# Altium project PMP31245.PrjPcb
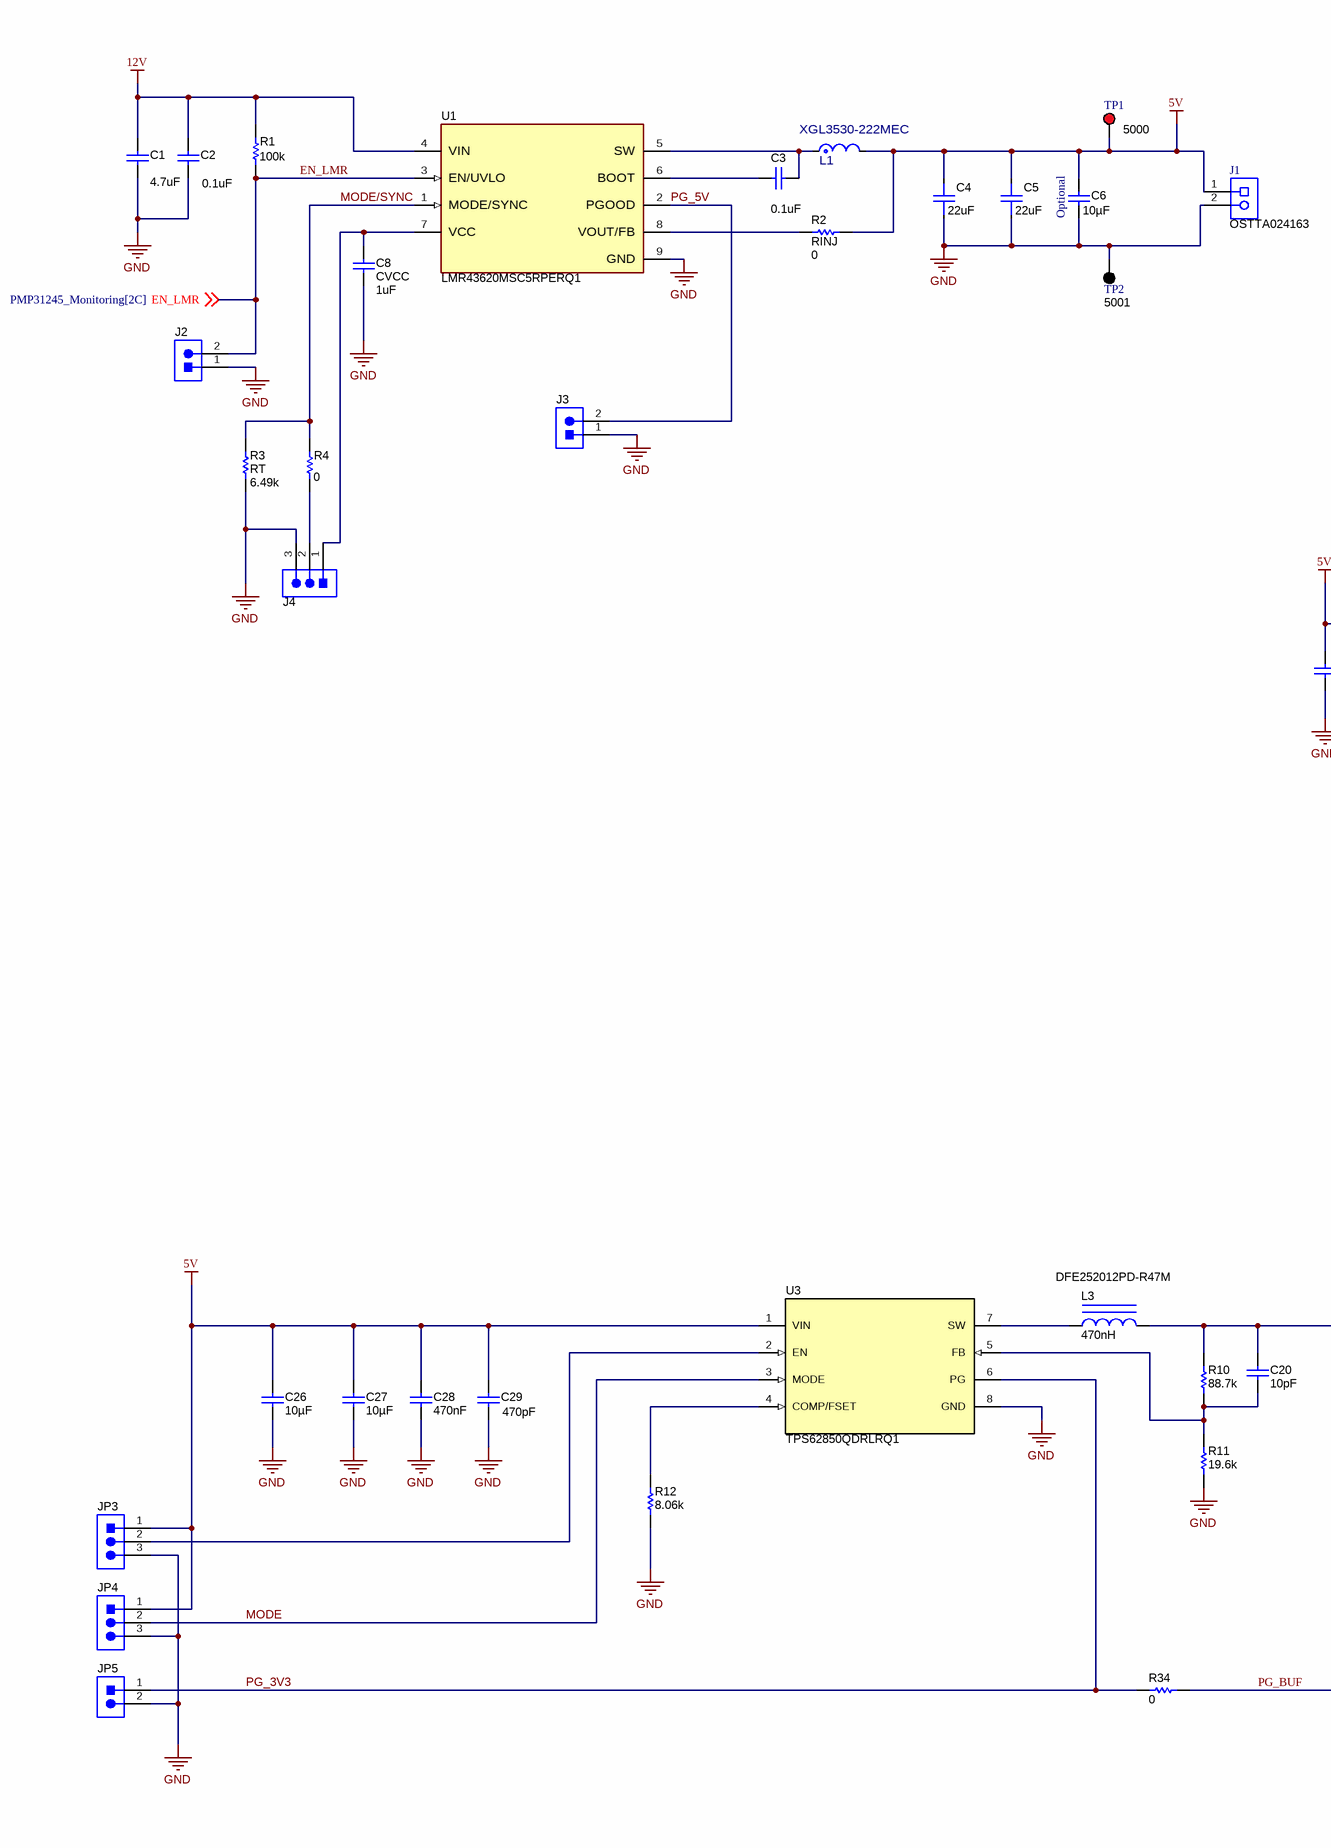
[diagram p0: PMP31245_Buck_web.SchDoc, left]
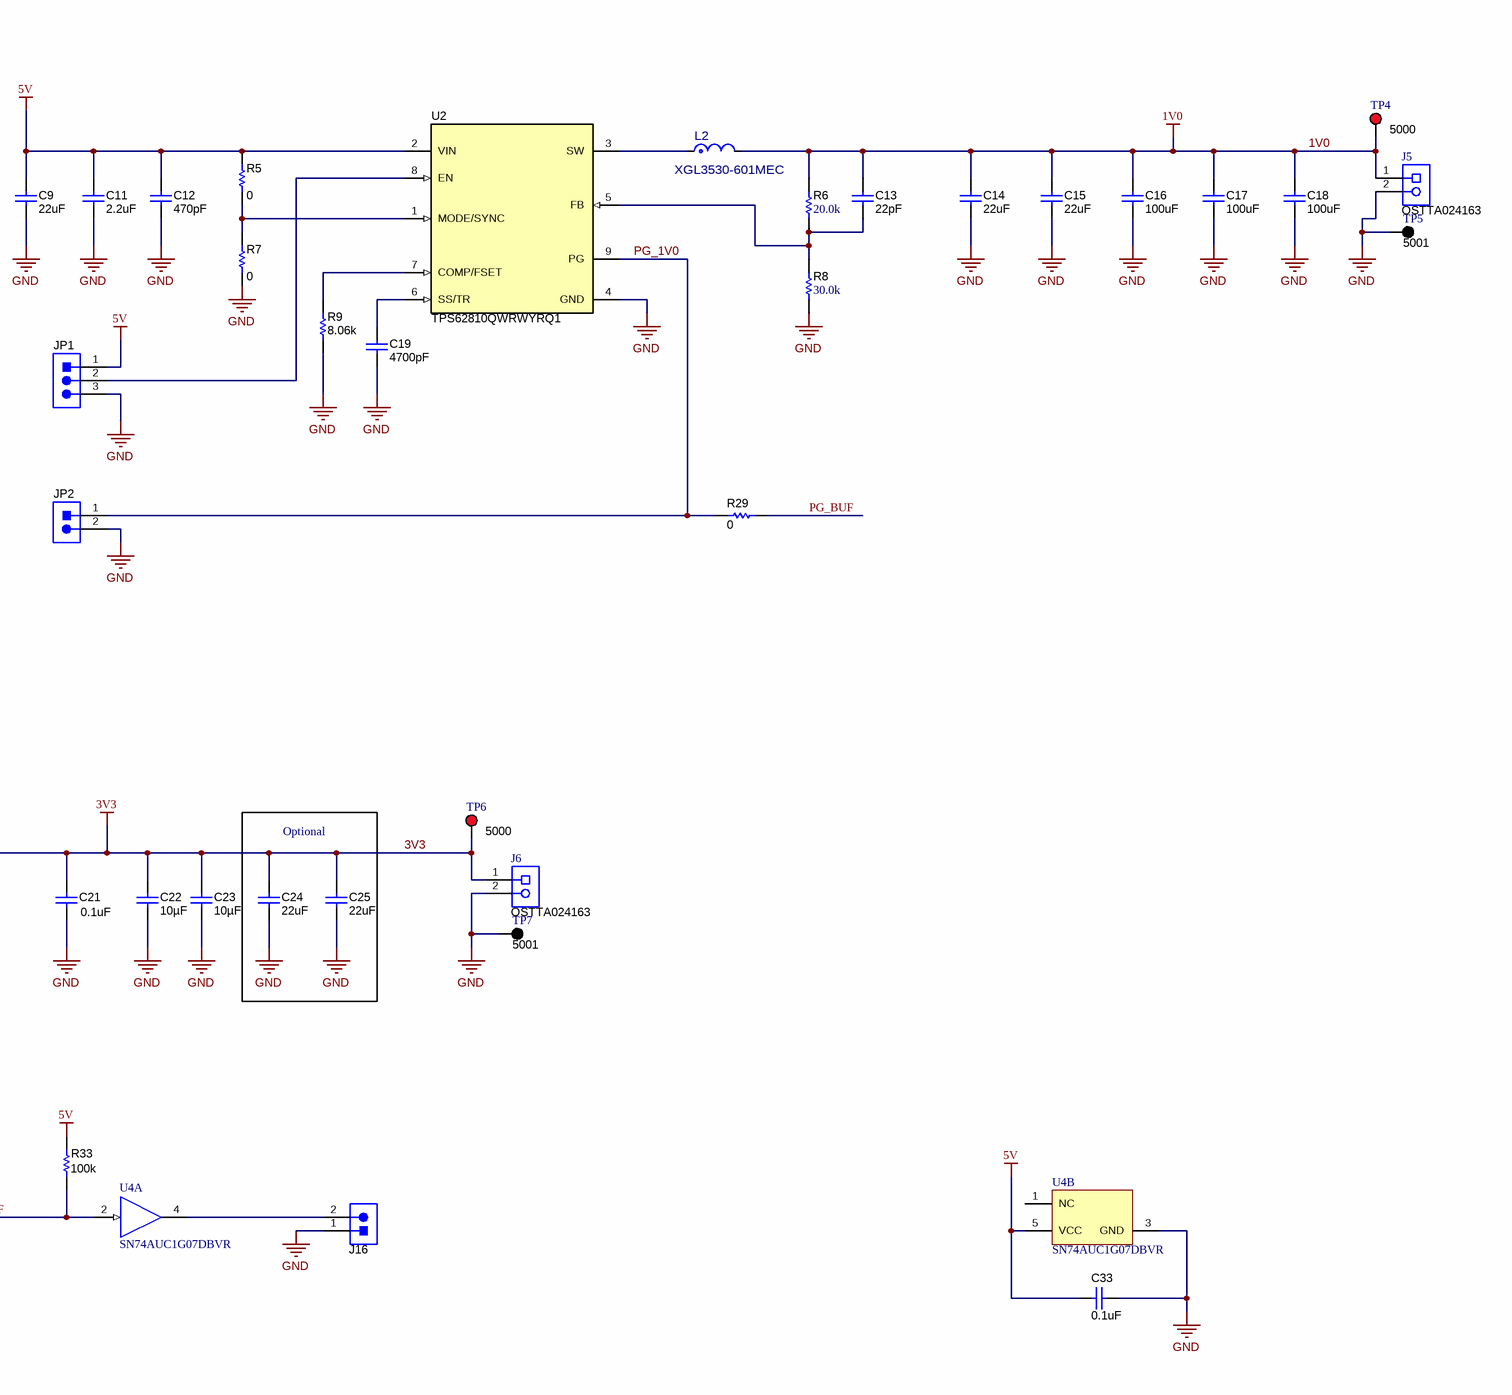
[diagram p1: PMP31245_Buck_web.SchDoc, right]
PCB_Rev: E1; SCH_Rev: E1; PRJ_Title: Automotive MCU Power Tree; PRJ_Number: PMP31245; PRJ_Engineer: Björn Görner; EVM_orderable: No; DrawnBy: Björn Görner
3 sheets, 132 parts. Net scope: global (net labels, ports and power ports of the same name join across sheets).
Board file: PMP31245.PcbDoc
Sheets:
  PMP31245_Buck_web.SchDoc
  PMP31245_Boost.SchDoc
  PMP31245_Monitoring.SchDoc

## Sheet PMP31245_Buck_web.SchDoc
size A2; Date: Not shown in title block; ApprovedBy: Not shown in title block; CheckedBy: Not shown in title block; Author: Not shown in title block; CompanyName: Not shown in title block; Engineer: Not shown in title block; Organization: Not shown in title block; Address1: Not shown in title block; Address2: Not shown in title block; Address3: Not shown in title block; Address4: Not shown in title block; DocumentNumber: 1; Revision: Use project parameter SCH_Rev; SheetNumber: 1; SheetTotal: 3; PageSetup: Record=PageOptions¦CenterHorizontal=True¦CenterVertical=True¦PrintScale=0.69¦XCorrection=1.00¦YCorrection=1.00¦PrintKind=0¦BorderSize=5000000¦LeftOffset=0¦BottomOffset=0¦Orientation=2¦PaperLength=1000¦PaperWidth=1000¦Scale=100¦PaperSource=15¦PrintQuality=600¦MediaType=1¦DitherType=10¦PaperKind=Letter¦PrintScaleMode=1

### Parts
C1  ValueDisplayed: 4.7uF  [1206_180L]  (hidden comment: CIN)
C2  ValueDisplayed: 0.1uF  [0402L]  (hidden comment: CINHF)
C3  ValueDisplayed: 0.1uF  [0402S]  (hidden comment: CB)
C4  ValueDisplayed: 22uF  [FP-GRM31CC81E226KE11L_1206-MFG]  (hidden comment: COUT1)
C5  ValueDisplayed: 22uF  [FP-GRM31CC81E226KE11L_1206-MFG]  (hidden comment: COUT2)
C6  ValueDisplayed: 10µF  [1206_190]  (hidden comment: COUT3)
C8  CVCC  ValueDisplayed: 1uF  [0603S]
C9  ValueDisplayed: 22uF  [1206_180L]  (hidden comment: GCM31CR71A226KE02)
C11  ValueDisplayed: 2.2uF  [0603L]  (hidden comment: GCM188C71A225K)
C12  ValueDisplayed: 470pF  [0402L]  (hidden comment: GCM155R71H471KA37D)
C13  ValueDisplayed: 22pF  [0402]  (hidden comment: GCM1555C1H220JA16D)
C14  ValueDisplayed: 22uF  [1206_180L]  (hidden comment: GCM31CR71A226KE02)
C15  ValueDisplayed: 22uF  [1206_180L]  (hidden comment: GCM31CR71A226KE02)
C16  ValueDisplayed: 100uF  [1210_270]  (hidden comment: GRM32ER60J107ME20L)
C17  ValueDisplayed: 100uF  [1210_270]  (hidden comment: GRM32ER60J107ME20L)
C18  ValueDisplayed: 100uF  [1210_270]  (hidden comment: GRM32ER60J107ME20L)
C19  ValueDisplayed: 4700pF  [0402]  (hidden comment: GCM155R71H472KA37D)
C20  ValueDisplayed: 10pF  [0402S]  (hidden comment: GCM1555C1H100JA16D)
C21  ValueDisplayed: 0.1uF  [0402S]  (hidden comment: C0402C104K4RACAUTO)
C22  Cap_F: 10µF  [0603]  (hidden comment: GRM188Z71A106MA73D)
C23  Cap_F: 10µF  [0603]  (hidden comment: GRM188Z71A106MA73D)
C24  ValueDisplayed: 22uF  [1206_180M]  (hidden comment: GCM31CR71A226KE02)
C25  ValueDisplayed: 22uF  [1206_180M]  (hidden comment: GCM31CR71A226KE02)
C26  Cap_F: 10µF  [0603]  (hidden comment: GRM188Z71A106MA73D)
C27  Cap_F: 10µF  [0603]  (hidden comment: GRM188Z71A106MA73D)
C28  Cap_F: 470nF  [0603S]  (hidden comment: GRM188R71C474KA88D)
C29  ValueDisplayed: 470pF  [0402S]  (hidden comment: CGA2B2X7R1H471K050BA)
C33  ValueDisplayed: 0.1uF  [0402S]  (hidden comment: C0402C104K4RACAUTO)
J1  OSTTA024163  [On-Shore_OSTTA024163]
J2  JEN  [Samtec_HTSW-102-07-G-S]  (value not drawn)
J3  JEN  [Samtec_HTSW-102-07-G-S]  (value not drawn)
J4  JMODE/SYNC  [Samtec_HTSW-103-07-G-S]  (value not drawn)
J5  OSTTA024163  [On-Shore_OSTTA024163]
J6  OSTTA024163  [On-Shore_OSTTA024163]
J16  JEN  [Samtec_HTSW-102-07-G-S]  (value not drawn)
JP1  61300311121  [WURTH_61300311121]  (value not drawn)
JP2  61300211121  [WURTH_61300211121]  (value not drawn)
JP3  61300311121  [WURTH_61300311121]  (value not drawn)
JP4  61300311121  [WURTH_61300311121]  (value not drawn)
JP5  61300211121  [WURTH_61300211121]  (value not drawn)
L1  XGL3530-222MEC  [FP-XGL3530-222MEC_SMT_IND_3MM2_3MM5-MFG]
L2  XGL3530-601MEC  [FP-XGL3530_SMT_IND_3MM2_3MM5-MFG]
L3  DFE252012PD-R47M  ValueDisplayed: 470nH  [DFE252012P]
R1  ValueDisplayed: 100k  [0402S]  (hidden comment: RENT)
R2  RINJ  ValueDisplayed: 0  [0402S]
R3  RT  ValueDisplayed: 6.49k  [0402S]
R4  ValueDisplayed: 0  [0603L]  (hidden comment: RJM)
R5  ValueDisplayed: 0  [0402S]  (hidden comment: RINJ)
R6  ValueDisplayed: 20.0k  [0402]  (hidden comment: CRCW040220K0FKED)
R7  ValueDisplayed: 0  [0402S]  (hidden comment: DNP)
R8  ValueDisplayed: 30.0k  [0402]  (hidden comment: CRCW040230K0FKED)
R9  ValueDisplayed: 8.06k  [0402]  (hidden comment: CRCW04028K06FKED)
R10  ValueDisplayed: 88.7k  [0402S]  (hidden comment: CRCW040280K6FKED)
R11  ValueDisplayed: 19.6k  [0402S]  (hidden comment: CRCW040240K2FKED)
R12  ValueDisplayed: 8.06k  [0402S]  (hidden comment: CRCW04028K06FKED)
R29  ValueDisplayed: 0  [0402S]  (hidden comment: RINJ)
R33  ValueDisplayed: 100k  [0402S]  (hidden comment: RENT)
R34  ValueDisplayed: 0  [0402S]  (hidden comment: RINJ)
TP1  5000  [Keystone5000]
TP2  5001  [Keystone5001]
TP4  5000  [Keystone5000]
TP5  5001  [Keystone5001]
TP6  5000  [Keystone5000]
TP7  5001  [Keystone5001]
U1  LMR43620MSC5RPERQ1  [RPE0009A-MFG]
U2  TPS62810QWRWYRQ1  [RWY0009A]
U3  TPS62850QDRLRQ1  [DRL0008A]
U4  SN74AUC1G07DBVR  [DBV0005A_N]  (parts A,B of 2)

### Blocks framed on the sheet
Optional: C24 C25

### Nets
1V0: C13.1 C14.1 C15.1 C16.1 C17.1 C18.1 J5.1 L2.2 R6.2 TP4.1
3V3: C20.1 C21.1 C22.1 C23.1 C24.1 C25.1 J6.1 L3.2 R10.2 TP6.1
5V: C4.2 C5.2 C6.2 C9.1 C11.1 C12.1 C26.1 C27.1 C28.1 C29.2 C33.1 J1.1 JP1.1 JP3.1 JP4.1 L1.2 R2.1 R5.1 R33.2 TP1.1 U2.2(VIN) U3.1(VIN) U4.5(VCC)
12V: C1.2 C2.1 R1.2 U1.4(VIN)
GND: C1.1 C2.2 C4.1 C5.1 C6.1 C8.2 C9.2 C11.2 C12.2 C14.2 C15.2 C16.2 C17.2 C18.2 C19.2 C21.2 C22.2 C23.2 C24.2 C25.2 C26.2 C27.2 C28.2 C29.1 C33.2 J1.2 J2.1 J3.1 J4.3 J5.2 J6.2 J16.1 JP1.3 JP2.2 JP3.3 JP4.3 JP5.2 R3.2 R7.2 R8.1 R9.1 R11.1 R12.1 TP2.1 TP5.1 TP7.1 U1.9(GND) U2.4(GND) U3.8(GND) U4.3(GND)
EN_LMR: J2.2 R1.1 U1.3(EN/UVLO) ; off-sheet EN_LMR
MODE: JP4.2 U3.3(MODE)
MODE/SYNC: R3.1 R4.2 U1.1(MODE/SYNC)
PG_1V0: JP2.1 R29.1 U2.9(PG)
PG_3V3: JP5.1 R34.1 U3.6(PG)
PG_5V: J3.2 U1.2(PGOOD)
PG_BUF: R29.2 R33.1 R34.2 U4.2(A)
NetC3_1: C3.1 U1.6(BOOT)
NetC3_2: C3.2 L1.1 U1.5(SW)
NetC8_1: C8.1 J4.1 U1.7(VCC)
NetC13_2: C13.2 R6.1 R8.2 U2.5(FB)
NetC19_1: C19.1 U2.6(SS/TR)
NetC20_2: C20.2 R10.1 R11.2 U3.5(FB)
NetJ4_2: J4.2 R4.1
NetJ16_2: J16.2 U4.4(Y)
NetJP1_2: JP1.2 U2.8(EN)
NetJP3_2: JP3.2 U3.2(EN)
NetL2_1: L2.1 U2.3(SW)
NetL3_1: L3.1 U3.7(SW)
NetR2_2: R2.2 U1.8(VOUT/FB)
NetR5_2: R5.2 R7.1 U2.1(MODE/SYNC)
NetR9_2: R9.2 U2.7(COMP/FSET)
NetR12_2: R12.2 U3.4(COMP/FSET)

Not connected (* = marked no-connect by the designer): U4 1(NC)

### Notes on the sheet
- (near C6) Optional

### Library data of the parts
C1 = CMP-0008969-2: CAP, CERM, 4.7 uF, 50 V, +/- 10%, X7R, 1206; Manufacturer: MuRata; PartNumber: GRM31CR71H475KA12L; TaMin_C: -55°C; Polarized: N; SizeAreaWB_mm2: 10.92; Value1: Unknown; U/M: EA; Value: 4.7uF; TaMax_C: 125°C; SizeZ_mm: 1.8; SizeX_mm: 3.2; SizeY_mm: 1.6; Cap_Case: 2220; Value2: 50V; SizeArea_mm2: 5.12; CompType: Capacitor; Cap_F: 4.7µF; AEC Category: Q200
C2 = CMP-0006356-2: CAP, CERM, 0.1 uF, 50 V, +/- 10%, X7R, AEC-Q200 Grade 1, 0402; Manufacturer: MuRata; PartNumber: GCM155R71H104KE02D; TaMin_C: -55°C; Polarized: N; SizeAreaWB_mm2: 3; Value1: Unknown; U/M: EA; Value: 0.1uF; TaMax_C: 125°C; SizeZ_mm: 0.6; SizeX_mm: 1; SizeY_mm: 0.5; Cap_Case: 0402; Value2: 50V; AEC Qualified: Y; Cap_F: 100nF; AEC Category: Q200
C3 = CMP-0006295-2: CAP, CERM, 0.1 uF, 25 V, +/- 20%, X7R, 0402; Manufacturer: TDK; PartNumber: C1005X7R1E104M050BB; TaMin_C: -55°C; Polarized: N; SizeAreaWB_mm2: 3; Value1: Unknown; U/M: EA; Value: 0.1uF; TaMax_C: 125°C; SizeZ_mm: 0.6; SizeX_mm: 1; SizeY_mm: 0.5; Cap_Case: 0402; Value2: 25V; CompType: Capacitor; Cap_F: 100nF; AEC Category: Q200
C4 C5 = CMP-0092611-1: Chip Multilayer Ceramic Capacitors for General Purpose, 1206, 22uF, X6S, 22%, 10%, 25V; Manufacturer: Murata; Part Number: GRM31CC81E226KE11L; Value: 22µF; AEC Qualified: No; SizeZ_mm: 1.9mm
C6 = CMP-0085950-1: CAP, CERM, 10 µF, 50 V,+/- 10%, X7R, AEC-Q200 Grade 1, 1206; Manufacturer: TDK; PartNumber: CGA5L1X7R1H106K160AC; SizeZ_mm: 1.9; Value: 10uF; Value2: 50V; Cap_Case: 1206; AEC Grade: 1; TaMin_C: -55°C; U/M: EA; CompType: Capacitor; SizeArea_mm2: 5.12; TaMax_C: 125°C; AEC Qualified: Y; AEC Category: Q200; SizeX_mm: 3.2; SizeY_mm: 1.6; Polarized: N; SizeAreaWB_mm2: 10.92
C8 = CMP-0006831-4: CAP, CERM, 1 uF, 16 V, +/- 10%, X7R, 0603; Manufacturer: Wurth Elektronik; PartNumber: 885012206052; TaMin_C: -55°C; Polarized: N; SizeAreaWB_mm2: 4.68; Value1: Unknown; U/M: EA; Value: 1uF; TaMax_C: 125°C; SizeZ_mm: 1; SizeX_mm: 1.6; SizeY_mm: 0.8; Cap_Case: 0603; Value2: 16V; SizeArea_mm2: 1.28; CompType: Capacitor; Cap_F: 1µF; AEC Category: Q200
C9 C14 C15 C24 C25 = CMP-0008811-2: CAP, CERM, 22 uF, 10 V, +/- 10%, X7R, AEC-Q200 Grade 1, 1206; Manufacturer: MuRata; Polarized: N; CompType: Capacitor; Value: 22uF; U/M: EA; Cap_F: 22µF; Value1: Unknown; VDC_V: 10V; TaMin_C: -55°C; TaMax_C: 125°C; Cap_Case: 1206; SizeArea_mm2: 5.12; SizeAreaWB_mm2: 10.92; SizeX_mm: 3.2; SizeY_mm: 1.6; SizeZ_mm: 1.8; AEC Category: Q200; AEC Qualified: Y; AEC Grade: 1
C11 = CMP-0007133-4: CAP, CERM, 2.2 uF, 10 V, +/- 10%, X7S, 0603; Manufacturer: MuRata; Alternate PartNumber: CGA3E3X7S1A225K080AB; Alternate Manufacturer: TDK; Polarized: N; CompType: Capacitor; Value: 2.2uF; U/M: EA; Cap_F: 2.2µF; Value1: Unknown; VDC_V: 10V; TaMin_C: -55°C; TaMax_C: 125°C; Cap_Case: 0603; SizeArea_mm2: 1.28; SizeAreaWB_mm2: 4.68; SizeX_mm: 1.6; SizeY_mm: 0.8; SizeZ_mm: 1; AEC Category: Q200
C12 = CMP-0006360-2: CAP, CERM, 470 pF, 50 V, +/- 10%, X7R, AEC-Q200 Grade 1, 0402; Manufacturer: MuRata; Polarized: N; CompType: Capacitor; Value: 470pF; U/M: EA; Value1: Unknown; VDC_V: 50V; TaMin_C: -55°C; TaMax_C: 125°C; Cap_Case: 0402; SizeArea_mm2: 0.5; SizeAreaWB_mm2: 3; SizeX_mm: 1; SizeZ_mm: 0.6; AEC Category: Q200; AEC Qualified: Y
C13 = CMP-0006348-2: CAP, CERM, 22 pF, 50 V, +/- 5%, C0G/NP0, AEC-Q200 Grade 1, 0402; Manufacturer: MuRata; Polarized: N; CompType: Capacitor; Value: 22pF; U/M: EA; Value1: Unknown; VDC_V: 50V; TaMin_C: -55°C; TaMax_C: 125°C; SizeArea_mm2: 0.5; SizeAreaWB_mm2: 3; SizeX_mm: 1; SizeZ_mm: 0.6; AEC Category: Q200; AEC Qualified: Y
C16-C18 = CMP-0009204-2: CAP, CERM, 100 uF, 6.3 V, +/- 20%, X5R, 1210; Manufacturer: MuRata; Polarized: N; CompType: Capacitor; Value: 100uF; U/M: EA; Cap_F: 100µF; ESR_ohm: 2m; Value1: 0.002 ohm; VDC_V: 6.3V; TaMin_C: -55°C; TaMax_C: 85°C; Cap_Case: 1210; SizeArea_mm2: 8; SizeAreaWB_mm2: 14.7; SizeX_mm: 3.2; SizeY_mm: 2.5; SizeZ_mm: 2.7; AEC Category: Q200
C19 = CMP-0006361-2: CAP, CERM, 4700 pF, 50 V, +/- 10%, X7R, AEC-Q200 Grade 1, 0402; Manufacturer: MuRata; Polarized: N; CompType: Capacitor; Value: 4700pF; U/M: EA; Cap_F: 4.7nF; Value1: Unknown; VDC_V: 50V; TaMin_C: -55°C; TaMax_C: 125°C; SizeArea_mm2: 0.5; SizeAreaWB_mm2: 3; SizeX_mm: 1; SizeZ_mm: 0.6; AEC Category: Q200; AEC Qualified: Y
C20 = CMP-0860290-1: CAP, CERM, 10 pF, 50 V,+/- 5%, C0G/NP0, AEC-Q200 Grade 1, 0402; Manufacturer: MuRata; TaMin_C: -55°C; AEC Grade: 1; AEC Qualified: Y; SizeAreaWB_mm2: 3; Cap_Case: 0402; SizeZ_mm: 0.6; Value: 10pF; TaMax_C: 125°C; Polarized: N; Value2: 50V; SizeArea_mm2: 0.5; U/M: EA; AEC Category: Q200
C21 C33 = CMP-0006237-2: CAP, CERM, 0.1 uF, 16 V, +/- 10%, X7R, AEC-Q200 Grade 1, 0402; Manufacturer: Kemet; TaMin_C: -55°C; Polarized: N; SizeAreaWB_mm2: 3; Value1: Unknown; U/M: EA; Value: 0.1uF; TaMax_C: 125°C; SizeZ_mm: 0.6; SizeX_mm: 1; SizeY_mm: 0.5; Cap_Case: 0402; Value2: 16V; AEC Qualified: Y; Cap_F: 100nF; AEC Category: Q200
C22 C23 C26 C27 = CMP-0007497-5: CAP, CERM, 10 uF, 10 V, +/- 20%, X7R, 0603; Manufacturer: MuRata; TaMin_C: -55°C; Polarized: N; SizeAreaWB_mm2: 4.68; Value1: Unknown; U/M: EA; Value: 10uF; TaMax_C: 125°C; SizeZ_mm: 1; SizeX_mm: 1.6; SizeY_mm: 0.8; Value2: 10V; SizeArea_mm2: 1.28; AEC Category: Q200
C28 = CMP-0007398-4: CAP, CERM, 0.47 uF, 16 V, +/- 10%, X7R, 0603; Manufacturer: MuRata; TaMin_C: -55°C; Polarized: N; SizeAreaWB_mm2: 4.68; Value1: Unknown; U/M: EA; Value: 0.47uF; TaMax_C: 125°C; SizeZ_mm: 1; SizeX_mm: 1.6; SizeY_mm: 0.8; Cap_Case: 0603; Value2: 16V; SizeArea_mm2: 1.28; AEC Category: Q200
C29 = CMP-0006320-2: CAP, CERM, 470 pF, 50 V, +/- 10%, X7R, AEC-Q200 Grade 1, 0402; Manufacturer: TDK; TaMin_C: -55°C; ESR_ohm: 4.96489; Polarized: N; SizeAreaWB_mm2: 3; Value1: 4.96489 ohm; U/M: EA; Value: 470pF; TaMax_C: 125°C; SizeZ_mm: 0.6; SizeX_mm: 1; SizeY_mm: 0.5; Cap_Case: 0402; Value2: 50V; AEC Qualified: Y; IRMS_A: 228.414mA; AEC Category: Q200
J1 J5 J6 = CMP-0074959-1: Terminal Block, 2x1, 5.08mm, TH; Manufacturer: On-Shore Technology; CT: True; Green_REACh: Incomplete; CNHeader: False; Green_Lifecycle: Not Set
J2 J3 J16 = CMP-0075483-1: Header, 100mil, 2x1, Gold, TH; PartNumber: HTSW-102-07-G-S; Manufacturer: Samtec; Green_REACh: Passed; CT: False; Green_Lifecycle: Active; CNHeader: True
J4 = CMP-0075484-1: Header, 100mil, 3x1, Gold, TH; PartNumber: HTSW-103-07-G-S; Manufacturer: Samtec; Green_REACh: Passed; CT: False; Green_Lifecycle: Active; CNHeader: True
JP1 JP3 JP4 = CMP-0054796-2: Header, 2.54 mm, 3x1, Gold, TH; Manufacturer: Wurth Elektronik; Pitch_mm: 2.54; Green_Lifecycle: Active; Cert_UL: Y; Shrouded: N; Green_REACh: Passed; Gender: Male; Row_Count: 1
JP2 JP5 = CMP-0054794-2: Header, 2.54 mm, 2x1, Gold, TH; Manufacturer: Wurth Elektronik; Shrouded: N; Gender: Male; Green_REACh: Passed; Pitch_mm: 2.54; Green_Lifecycle: Active; Row_Count: 1; Cert_UL: Y
L1 = CMP-0091207-1: Molded Power Inductor, Shielded, 2.2uH 20%, 7.2A, 23mOhm DCR Max, AEC-Q200, T/R; Manufacturer: Coilcraft; TaMin_C: -40°C; DCR_ohm: 23m; AEC Qualified: Yes; TaMax_C: +125°C; AEC Grade: Grade 1; Ind_H: 2.2µH; SizeZ_mm: 3mm; Shrouded: true; Isat: 1.9A; Test Frequency: 1MHz; Self Resonant Frequency: 52MHz; Material: Composite
L2 = CMP-0092762-2: Power Inductor, shielded, composite, 20% tol, SMT, RoHS, halogen-free   USD 0.580; Part Number: XGL3530-332MEC; Manufacturer: Coilcraft; Ind_H: 3.3µH; Value: 3.3uH; Self Resonant Frequency: 43MHz; TaMax_C: +125°C; TaMin_C: -40°C; AEC Qualified: Yes; Isat: 1.6A; DCR_ohm: 37.4m; SizeZ_mm: 3mm; Irms: 5.4A; Test Frequency: 1MHz; Shrouded: true; AEC Grade: Grade 1
L3 = CMP-0058944-1: Inductor, Shielded, 470 nH, 4.7 A, 0.021 ohm, SMD; Manufacturer: MuRata Toko; Isat: 6.1A @ 30% inductance drop; Irms: 4.7A @ 40C rise; SizeAreaWB_mm2: 10.5; DCR_ohm: 0.021; Value: 470nH; Imax_A: 4.7A; SizeZ_mm: 1.2; SizeX_mm: 2.5; SizeY_mm: 2; SizeArea_mm2: 5; AEC Category: Q200
R1 R33 = CMP-0025950-3: RES, 100 k, 1%, 0.063 W, AEC-Q200 Grade 0, 0402; Manufacturer: Vishay-Dale; PartNumber: CRCW0402100KFKED; Power_W: 63mW; TempCo: 100 ppm/C; Value: 100k; EIA_Code: E96; SizeX_mm: 1; SizeY_mm: 0.5; SizeZ_mm: 0.6; Value2: 0.063W; CompType: Resistor; AEC Qualified: Y; VDC_V: 50V; AEC Category: Q200; AEC Grade: 0
R2 R5 R7 R29 R34 = CMP-0026822-3: RES, 0, 5%, 0.063 W, AEC-Q200 Grade 0, 0402; Manufacturer: Vishay-Dale; PartNumber: CRCW04020000Z0ED; Power_W: 63mW; TempCo: 200 ppm/C; Value_Code: 0000; Value: 0; EIA_Code: E24; SizeX_mm: 1; SizeY_mm: 0.5; SizeZ_mm: 0.6; Value2: 0.063W; AEC Qualified: Y; VDC_V: 50V; AEC Category: Q200
R3 = CMP-0026515-2: RES, 6.49 k, 1%, 0.063 W, AEC-Q200 Grade 0, 0402; Manufacturer: Vishay-Dale; PartNumber: CRCW04026K49FKED; Power_W: 63mW; TempCo: 100 ppm/C; Value_Code: 6k49; Value: 6.49k; EIA_Code: E96; SizeX_mm: 1; SizeY_mm: 0.5; SizeZ_mm: 0.6; Value2: 0.063W; CompType: Resistor; AEC Qualified: Y; VDC_V: 50V; AEC Category: Q200; AEC Grade: 0
R4 = CMP-0025697-4: RES, 0, 5%, 0.1 W, AEC-Q200 Grade 0, 0603; Manufacturer: Vishay-Dale; PartNumber: CRCW06030000Z0EA; Power_W: 100mW; TempCo: 200 ppm/C; Value_Code: 0000; Value: 0; EIA_Code: E24; SizeX_mm: 1.6; SizeY_mm: 0.8; SizeZ_mm: 1; Value2: 0.1W; SizeArea_mm2: 1.28; AEC Qualified: Y; VDC_V: 75V; AEC Category: Q200
R6 = CMP-0026162-2: RES, 20.0 k, 1%, 0.063 W, AEC-Q200 Grade 0, 0402; Manufacturer: Vishay-Dale; Power_W: 63mW; TempCo: 100 ppm/C; Value_Code: 20k0; Value: 20.0k; EIA_Code: E96; Res_ohm: 20k; SizeX_mm: 1; SizeY_mm: 0.5; SizeZ_mm: 0.6; Value2: 0.063W; AEC Qualified: Y; VDC_V: 50V; AEC Category: Q200; AEC Grade: 0
R8 = CMP-0078244-2: RES, 30.0 k, 1%, 0.063 W, AEC-Q200 Grade 0, 0402; Manufacturer: Vishay-Dale; Power_W: 63mW; Green_Lifecycle: Active; TempCo: 100 ppm/C; Value_Code: 30k0; Green_REACh: Passed; Value: 30.0k; Res_ohm: 30k; SizeX_mm: 1; SizeY_mm: 0.5; SizeZ_mm: 0.6; Value2: 0.063W; AEC Qualified: Y; VDC_V: 50V; AEC Grade: 0; AEC Category: Q200
R9 R12 = CMP-0026588-2: RES, 8.06 k, 1%, 0.063 W, AEC-Q200 Grade 0, 0402; Manufacturer: Vishay-Dale; Value: 8.06k; Value_Code: 8k06; Power_W: 63mW; Value2: 0.063W; VDC_V: 50V; TempCo: 100 ppm/C; SizeArea_mm2: 0.5; SizeX_mm: 1; SizeZ_mm: 0.6; EIA_Code: E96; AEC Category: Q200; AEC Qualified: Y; AEC Grade: 0
R10 = CMP-0026570-2: RES, 80.6 k, 1%, 0.063 W, AEC-Q200 Grade 0, 0402; Manufacturer: Vishay-Dale; Value: 80.6k; Value_Code: 80k6; Power_W: 63mW; Value2: 0.063W; VDC_V: 50V; TempCo: 100 ppm/C; SizeArea_mm2: 0.5; SizeX_mm: 1; SizeZ_mm: 0.6; EIA_Code: E96; AEC Category: Q200; AEC Qualified: Y; AEC Grade: 0
R11 = CMP-0026367-2: RES, 40.2 k, 1%, 0.063 W, AEC-Q200 Grade 0, 0402; Manufacturer: Vishay-Dale; Value: 40.2k; Value_Code: 40k2; Power_W: 63mW; Value2: 0.063W; VDC_V: 50V; TempCo: 100 ppm/C; SizeArea_mm2: 0.5; SizeX_mm: 1; SizeZ_mm: 0.6; EIA_Code: E96; AEC Category: Q200; AEC Qualified: Y; AEC Grade: 0
TP1 TP4 TP6 = CMP-0055137-1: Test Point, Miniature, Red, TH; Manufacturer: Keystone; CNHeader: FALSE; Green_Lifecycle: Active; Green_REACh: Passed; ContactFinish: Silver; CT: TRUE
TP2 TP5 TP7 = CMP-0055138-2: Test Point, Miniature, Black, TH; Manufacturer: Keystone Electronics; ContactFinish: Silver; CNHeader: FALSE; Green_Lifecycle: Active; Green_REACh: Passed; CT: TRUE
U1 = CMP-0091397-1: 36-V, 2-A Buck Converter with 1.5 µA IQ in 2-mm x 2-mm HotRod QFN; Manufacturer: Texas Instruments; Part Number: LMR43620MSC3RPERQ1; AEC Grade: Grade 1; Max Supply Voltage: 36V; Standoff Height: 0mm; Nominal Supply Current: 0.13uA; Max Duty Cycle: 98%; Switching Frequency: 2.2MHz; Output Type: Fixed,AdjustableProgrammable; TaMin_C: -40°C; SizeZ_mm: 1mm; TaMax_C: +125°C; TJmax_C: +150°C; Number Of Outputs: 1; AEC Qualified: Yes; Output Voltage: 1-34.2V; Min Supply Voltage: 3V
U2 = CMP-0082642-1: Automotive Low Input Voltage, Adjustable-Frequency Step-down Converter, RWY0009A (VQFN-HR-9); Alternate Manufacturer: Texas Instruments; SizeAreaWB_mm2: 12; SizeZ_mm: 1; SizeX_mm: 2; SizeY_mm: 3; SizeArea_mm2: 6; CompType: IC; AEC Qualified: Y; AEC Category: Q200
U3 = CMP-0860101-1: 2.7-V to 6-V Adjustable-Frequency Step-Down Converter, DRL0008A (SOT-5X3-8); Manufacturer: Texas Instruments; AEC Category: Q200; SizeX_mm: 1.6; SizeZ_mm: 0.6; AEC Qualified: Y; SizeY_mm: 2.1; SizeArea_mm2: 3.36; CompType: IC; SizeAreaWB_mm2: 8.06
U4 = CMP-0051406-2: Single Buffer/Driver With Open-Drain Output, DBV0005A (SOT-23-5); Manufacturer: Texas Instruments; 3-State Output: No; VCC(Max)(V): 2.7; Rating: Catalog; Input Type: CMOS; Logic: True; VCC(Min)(V): 0.8; F @ Nom Voltage(Max)(Mhz): 250; tpd @ Nom Voltage(Max)(ns): 4.7,3.3,2.4,2.3,1.8; ICC @ Nom Voltage(Max)(mA): 0.01; Voltage(Nom)(V): 0.8,1.2,1.5,1.8,2.5; Output Drive (IOL/IOH)(Max)(mA): 9/-9; Bits(#): 1; AEC Category: Q200; AEC Qualified: N; CompType: IC; SizeAreaWB_mm2: 14.82; SizeArea_mm2: 8.12; SizeX_mm: 2.8; SizeY_mm: 2.9; SizeZ_mm: 1.45

## Sheet PMP31245_Boost.SchDoc
size A3; Date: Not shown in title block; ApprovedBy: Not shown in title block; CheckedBy: Not shown in title block; Author: Not shown in title block; CompanyName: Not shown in title block; Engineer: Not shown in title block; Organization: Not shown in title block; Address1: Not shown in title block; Address2: Not shown in title block; Address3: Not shown in title block; Address4: Not shown in title block; DocumentNumber: 1; Revision: Use project parameter SCH_Rev; SheetNumber: 2; SheetTotal: 2; PageSetup: Record=PageOptions¦CenterHorizontal=True¦CenterVertical=True¦PrintScale=0.69¦XCorrection=1.00¦YCorrection=1.00¦PrintKind=0¦BorderSize=5000000¦LeftOffset=0¦BottomOffset=0¦Orientation=2¦PaperLength=1000¦PaperWidth=1000¦Scale=100¦PaperSource=15¦PrintQuality=600¦MediaType=1¦DitherType=10¦PaperKind=Letter¦PrintScaleMode=1
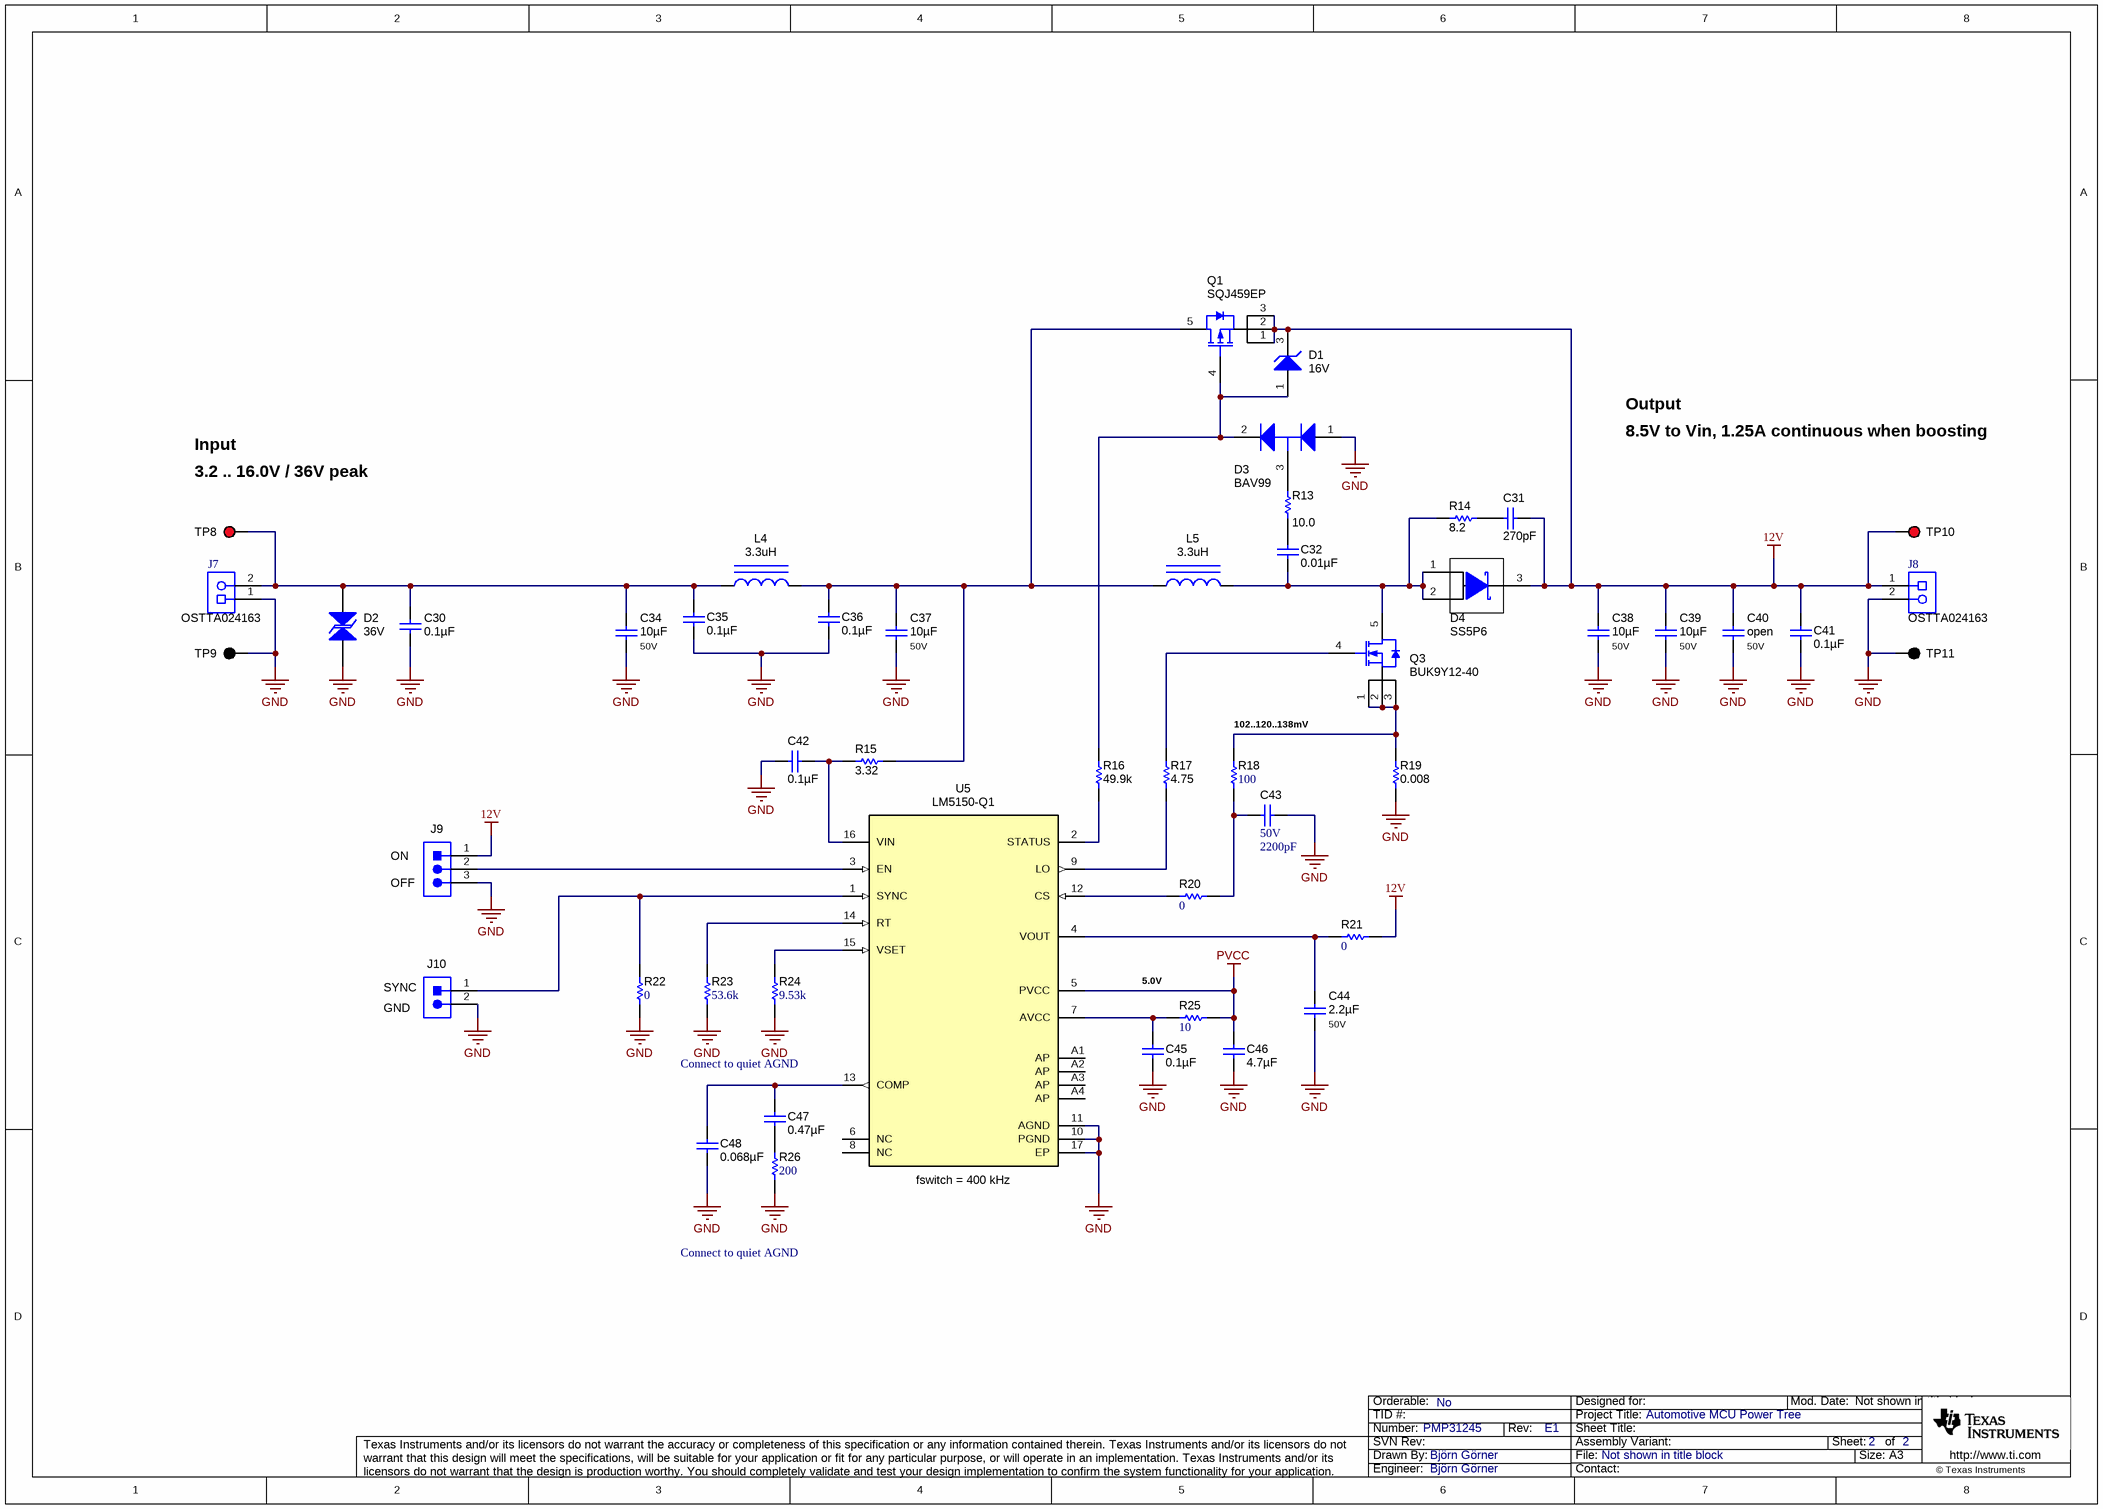
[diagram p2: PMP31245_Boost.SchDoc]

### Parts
C30  ValueDisplayed: 0.1µF  [0603]  (hidden comment: GRM188R71H104KA93D)
C31  ValueDisplayed: 270pF  [0603]  (hidden comment: GRM188R71H271KA01D)
C32  ValueDisplayed: 0.01µF  [0603]  (hidden comment: GRM188R72A103KA01D)
C34  ValueDisplayed: 10µF  Value2: 50V  [1210_270]  (hidden comment: GRM32ER71H106KA12L)
C35  ValueDisplayed: 0.1µF  [0603]  (hidden comment: GRM188R71H104KA93D)
C36  ValueDisplayed: 0.1µF  [0603]  (hidden comment: GRM188R71H104KA93D)
C37  ValueDisplayed: 10µF  Value2: 50V  [1210_270]  (hidden comment: GRM32ER71H106KA12L)
C38  ValueDisplayed: 10µF  Value2: 50V  [1210_270]  (hidden comment: GRM32ER71H106KA12L)
C39  ValueDisplayed: 10µF  Value2: 50V  [1210_270]  (hidden comment: GRM32ER71H106KA12L)
C40  ValueDisplayed: open  Value2: 50V  [1210_270]  (hidden comment: GRM32ER71H106KA12L)
C41  ValueDisplayed: 0.1µF  [0603]  (hidden comment: GRM188R71H104KA93D)
C42  ValueDisplayed: 0.1µF  [0603]  (hidden comment: GRM188R71H104KA93D)
C43  VDC_V: 50V  ValueDisplayed: 2200pF  [0402]  (hidden comment: CGA2B2X7R1H222K050BA)
C44  ValueDisplayed: 2.2µF  Value2: 50V  [1206_180]  (hidden comment: GRM31CR71H225KA88L)
C45  ValueDisplayed: 0.1µF  [0603]  (hidden comment: GRM188R71H104KA93D)
C46  ValueDisplayed: 4.7µF  [0805]  (hidden comment: GRM21BR71C475KA73L)
C47  ValueDisplayed: 0.47µF  [0603]  (hidden comment: GRM188R71E474KA12D)
C48  ValueDisplayed: 0.068µF  [0603]  (hidden comment: GRM188R71H683KA93D)
D1  value 16V  [SOT-23]  (hidden comment: BZX84C16LT1G)
D2  value 36V  [SMB]  (hidden comment: SMBJ36CA)
D3  BAV99  [SOT-23]
D4  SS5P6  [TO-277A]
J7  OSTTA024163  [On-Shore_OSTTA024163]
J8  OSTTA024163  [On-Shore_OSTTA024163]
J9  61300311121  [WURTH_61300311121]  (value not drawn)
J10  61300211121  [WURTH_61300211121]  (value not drawn)
L4  ValueDisplayed: 3.3uH  [VCHA042A]  (hidden comment: VCHA054T-3R3MS6)
L5  ValueDisplayed: 3.3uH  [VCHA042A]  (hidden comment: VCHA054T-3R3MS6)
Q1  SQJ459EP  [PowerPAK_SO-8L]
Q3  BUK9Y12-40  [PowerPAK_SO-8L]
R13  ValueDisplayed: 10.0  [0603]  (hidden comment: CRCW060310R0FKEA)
R14  ValueDisplayed: 8.2  [1206]  (hidden comment: CRCW12068R20JNEA)
R15  ValueDisplayed: 3.32  [0603]  (hidden comment: CRCW06033R32FKEA)
R16  ValueDisplayed: 49.9k  [0603]  (hidden comment: CRCW060349K9FKEA)
R17  ValueDisplayed: 4.75  [0603]  (hidden comment: CRCW06034R75FKEA)
R18  ValueDisplayed: 100  [0402]  (hidden comment: RMCF0402JT100R)
R19  ValueDisplayed: 0.008  [0612]  (hidden comment: PRL1632-R008-F-T1)
R20  ValueDisplayed: 0  [0402]  (hidden comment: ERJ-2GE0R00X)
R21  ValueDisplayed: 0  [0402]  (hidden comment: ERJ-2GE0R00X)
R22  ValueDisplayed: 0  [0402]  (hidden comment: ERJ-2GE0R00X)
R23  ValueDisplayed: 53.6k  [0402]  (hidden comment: CRCW040253K6FKED)
R24  ValueDisplayed: 9.53k  [0402]  (hidden comment: CRCW04029K53FKED)
R25  ValueDisplayed: 10  [0402]  (hidden comment: CRCW040210R0JNED)
R26  ValueDisplayed: 200  [0402]  (hidden comment: CRCW0402200RFKED)
TP8  5000  [Keystone5000]  (value not drawn)
TP9  5001  [Keystone5001]  (value not drawn)
TP10  5000  [Keystone5000]  (value not drawn)
TP11  5001  [Keystone5001]  (value not drawn)
U5  LM5150-Q1  [RUM0016C]

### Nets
12V: C31.1 C38.1 C39.1 C40.1 C41.1 D1.3(K) D4.3(K) J8.1 J9.1 Q1.1(S) Q1.2(S) Q1.3(S) R21.2 TP10.1
GND: C30.1 C34.2 C35.1 C36.1 C37.2 C38.2 C39.2 C40.2 C41.2 C42.1 C43.1 C44.2 C45.2 C46.1 C48.2 D2.1 D3.1(A) J7.1 J8.2 J9.3 J10.2 R19.1 R22.1 R23.1 R24.1 R26.1 TP9.1 TP11.1 U5.10(PGND) U5.11(AGND) U5.17(EP)
PVCC: C46.2 R25.2 U5.5(PVCC)
NetC30_2: C30.2 C34.1 C35.2 D2.2 J7.2 L4.1 TP8.1
NetC31_2: C31.2 R14.2
NetC32_1: C32.1 R13.1
NetC32_2: C32.2 D4.1(A) D4.2(A) L5.2 Q3.5(D) R14.1
NetC36_2: C36.2 C37.1 L4.2 L5.1 Q1.5(D) R15.1
NetC42_2: C42.2 R15.2 U5.16(VIN)
NetC43_2: C43.2 R18.1 R20.2
NetC44_1: C44.1 R21.1 U5.4(VOUT)
NetC45_1: C45.1 R25.1 U5.7(AVCC)
NetC47_1: C47.1 C48.1 U5.13(COMP)
NetC47_2: C47.2 R26.2
NetD1_1: D1.1(A) D3.2(K) Q1.4(G) R16.1
NetD3_3: D3.3(C) R13.2
NetJ9_2: J9.2 U5.3(EN)
NetJ10_1: J10.1 R22.2 U5.1(SYNC)
NetQ3_1: Q3.1(S) Q3.2(S) Q3.3(S) R18.2 R19.2
NetQ3_4: Q3.4(G) R17.2
NetR16_2: R16.2 U5.2(STATUS)
NetR17_1: R17.1 U5.9(LO)
NetR20_1: R20.1 U5.12(CS)
NetR23_2: R23.2 U5.14(RT)
NetR24_2: R24.2 U5.15(VSET)

Not connected (* = marked no-connect by the designer): U5 6(NC) 8(NC) A1(AP) A2(AP) A3(AP) A4(AP)

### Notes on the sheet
- Input
- Output
- 8.5V to Vin, 1.25A continuous when boosting
- (near TP8) 3.2 .. 16.0V / 36V peak
- (near R18) 102..120..138mV
- (near J9) ON
- (near J9) OFF
- (near J10) SYNC
- (near R25) 5.0V
- (near J10) GND
- Connect to quiet AGND
- (near U5) fswitch = 400 kHz

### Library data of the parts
C30 C35 C36 C41 C42 C45 = GRM188R71H104KA93D: CAP, CERM, 0.1 µF, 50 V, +/- 10%, X7R, 0603; Manufacturer: MuRata; Polarized: N; CompType: Capacitor; Value: 0.1uF; U/M: EA; Cap_F: 0.0000001; Tolerance_%: 10; Value1: Unknown; VDC_V: 50; Value2: 50V; TaMin_C: -55; TaMax_C: 125; SizeArea_mm2: 1.28; SizeAreaWB_mm2: 4.68; SizeX_mm: 1.6; SizeY_mm: 0.8; SizeZ_mm: 1; AEC Category: Q200
C31 = GRM188R71H271KA01D: CAP, CERM, 270 pF, 50 V,+/- 10%, X7R, 0603; Manufacturer: MuRata; Polarized: N; CompType: Capacitor; Value: 270pF; U/M: EA; Cap_F: 0.00000000027; Tolerance_%: 10; VDC_V: 50; Value2: 50V; TaMin_C: -55; TaMax_C: 125; SizeArea_mm2: 1.28; SizeAreaWB_mm2: 4.68; SizeX_mm: 1.6; SizeY_mm: 0.8; SizeZ_mm: 1; AEC Category: Q200
C32 = GRM188R72A103KA01D: CAP, CERM, 0.01 µF, 100 V, +/- 10%, X7R, 0603; Manufacturer: MuRata; Polarized: N; CompType: Capacitor; Value: 0.01uF; U/M: EA; Cap_F: 0.00000001; Tolerance_%: 10; Value1: Unknown; VDC_V: 100; Value2: 100V; TaMin_C: -55; TaMax_C: 125; SizeArea_mm2: 1.28; SizeAreaWB_mm2: 4.68; SizeX_mm: 1.6; SizeY_mm: 0.8; SizeZ_mm: 1; AEC Category: Q200
C34 C37-C40 = GRM32ER71H106KA12L: CAP, CERM, 10 µF, 50 V, +/- 10%, X7R, 1210; Manufacturer: MuRata; Polarized: N; CompType: Capacitor; Value: 10uF; U/M: EA; Cap_F: 0.00001; Tolerance_%: 10; Value1: Unknown; VDC_V: 50; TaMin_C: -55; TaMax_C: 125; Cap_Case: 1210; SizeArea_mm2: 8; SizeAreaWB_mm2: 14.7; SizeX_mm: 3.2; SizeY_mm: 2.5; SizeZ_mm: 2.7; AEC Category: Q200
C43 = CMP-0006317-2: CAP, CERM, 2200 pF, 50 V, +/- 10%, X7R, AEC-Q200 Grade 1, 0402; Manufacturer: TDK; TaMin_C: -55°C; ESR_ohm: 1.0779; Polarized: N; SizeAreaWB_mm2: 3; Value1: 1.07794 ohm; U/M: EA; Value: 2200pF; TaMax_C: 125°C; SizeZ_mm: 0.6; SizeX_mm: 1; SizeY_mm: 0.5; AEC Qualified: Y; Cap_F: 2.2nF; IRMS_A: 264.071mA; AEC Category: Q200
C44 = GRM31CR71H225KA88L: CAP, CERM, 2.2 µF, 50 V, +/- 10%, X7R, 1206; Manufacturer: MuRata; Polarized: N; CompType: Capacitor; Value: 2.2uF; U/M: EA; Cap_F: 0.0000022; Tolerance_%: 10; Value1: Unknown; VDC_V: 50; TaMin_C: -55; TaMax_C: 125; Cap_Case: 1206; SizeArea_mm2: 5.12; SizeAreaWB_mm2: 10.92; SizeX_mm: 3.2; SizeY_mm: 1.6; SizeZ_mm: 1.8; AEC Category: Q200
C46 = GRM21BR71C475KA73L: CAP, CERM, 4.7 µF, 16 V, +/- 10%, X7R, 0805; Manufacturer: MuRata; Polarized: N; CompType: Capacitor; Value: 4.7uF; U/M: EA; Cap_F: 0.0000047; Tolerance_%: 10; ESR_ohm: 0.006; Value1: 0.006 ohm; VDC_V: 16; Value2: 16V; TaMin_C: -55; TaMax_C: 125; SizeArea_mm2: 2.5; SizeAreaWB_mm2: 6.75; SizeX_mm: 2; SizeY_mm: 1.25; SizeZ_mm: 1.45; AEC Category: Q200
C47 = GRM188R71E474KA12D: CAP, CERM, 0.47 µF, 25 V,+/- 10%, X7R, 0603; Manufacturer: MuRata; Polarized: N; CompType: Capacitor; Value: 0.47uF; U/M: EA; Cap_F: 0.00000047; Tolerance_%: 10; VDC_V: 25; Value2: 25V; TaMin_C: -55; TaMax_C: 125; SizeArea_mm2: 1.28; SizeAreaWB_mm2: 4.68; SizeX_mm: 1.6; SizeY_mm: 0.8; SizeZ_mm: 1; AEC Category: Q200; Green_Lifecycle: Active; Green_REACh: Passed
C48 = GRM188R71H683KA93D: CAP, CERM, 0.068 µF, 50 V,+/- 10%, X7R, 0603; Manufacturer: MuRata; Polarized: N; CompType: Capacitor; Value: 0.068uF; U/M: EA; Cap_F: 0.000000068; Tolerance_%: 10; VDC_V: 50; Value2: 50V; TaMin_C: -55; TaMax_C: 125; SizeArea_mm2: 1.28; SizeAreaWB_mm2: 4.68; SizeX_mm: 1.6; SizeY_mm: 0.8; SizeZ_mm: 1; AEC Category: Q200; Green_Lifecycle: Active; Green_REACh: Passed
D1 = BZX84C16LT1G: Diode, Zener, 16 V, 225 mW, SOT-23; Manufacturer: ON Semiconductor; U/M: EA; Power_W: 0.225; Vz_V: 16; Value1: 0.225W; RJA_CperW: 556; SizeAreaWB_mm2: 14; SizeArea_mm2: 7.5; SizeX_mm: 2.5; SizeY_mm: 3; SizeZ_mm: 1.1; AEC Category: Q101
D2 = SMBJ33CA-13-F: Diode, TVS, Bi, 36 V, SMB; Manufacturer: Vishay-Semiconductor; U/M: EA; Power_W: 5; Vr_V: 36; Value1: 5W; SizeAreaWB_mm2: 44.156; SizeArea_mm2: 21.336; SizeX_mm: 5.6; SizeY_mm: 3.81; SizeZ_mm: 2.6; AEC Category: Q101
D3 = BAV99-7-F: Diode, Switching, 75 V, 0.3 A, SOT-23; Manufacturer: Diodes Inc.; SymbolCreator: a0412235; U/M: EA; Vf_V: 1.25; Value: 75V; Value1: 0.3A; Value2: 1.25V; Io_A: 0.3; Vr_V: 75; TJmax_C: 150; SizeAreaWB_mm2: 14; SizeArea_mm2: 7.5; SizeX_mm: 2.5; SizeY_mm: 3; SizeZ_mm: 1.1; AEC Category: Q101
D4 = SS5P6-M3/86A: Diode, Schottky, 60 V, 5 A, TO-277A; Manufacturer: Vishay-Semiconductor; U/M: EA; Vf_V: 0.69; Value: 60V; Value1: 5A; Value2: 0.69V; Io_A: 5; Vr_V: 60; TJmax_C: 150; SizeAreaWB_mm2: 57.375; SizeArea_mm2: 30.875; SizeX_mm: 6.5; SizeY_mm: 4.75; SizeZ_mm: 1.2; AEC Category: Q101; Green_Lifecycle: Not Set; Green_REACh: Incomplete
J7 J8 = CMP-0074959-1: as J1 on sheet PMP31245_Buck_web
J9 = 61300311121: Header, 2.54 mm, 3x1, Gold, TH; Manufacturer: Wurth Elektronik; SymbolCreator: a0799628; Green_Lifecycle: Active; Green_REACh: Passed
J10 = 61300211121: Header, 2.54 mm, 2x1, Gold, TH; Manufacturer: Wurth Elektronik; SymbolCreator: a0412235; Green_Lifecycle: Active; Green_REACh: Passed
L4 L5 = VCHA042A-1R0MS6: Inductor, 3.3 µH, 8.8 A, 0.028 ohm, AEC-Q200 Grade 0, SMD; Manufacturer: Cyntec; Value: 3.3uH; Imax_A: 8.8; DCR_ohm: 0.028; AEC Category: Q200; AEC Qualified: Y; AEC Grade: 0
Q1 = SQJ469EP-T1-GE3: MOSFET, P-CH, -60 V, -52 A, AEC-Q101, PowerPAK_SO-8L; PartNumber: SQJ459EP-T1_GE3; Manufacturer: Vishay-Siliconix; Alternate Manufacturer: None; SymbolCreator: a0411947; U/M: EA; ChType: P; Value: -60V; Value1: ? ohm; Value2: 73 nC; QgTyp_nC: 73; Vgs_V: -20; SizeAreaWB_mm2: 58.1095; SizeArea_mm2: 31.5495; SizeX_mm: 6.15; SizeY_mm: 5.13; SizeZ_mm: 1.14; AEC Category: Q101; AEC Qualified: Y
Q3 = SQJA60EP: MOSFET, N-CH, 60 V, 23 A, AEC-Q101, PowerPAK_SO-8L; PartNumber: SQJ158EP; Manufacturer: Vishay-Siliconix; Alternate Manufacturer: None; SymbolCreator: a0412235; U/M: EA; ChType: N; Value: 60V; VdsMax_V: 60; Value1: 0.03 ohm; Rdson45_ohm: 0.03; Value2: 17 nC; QgTyp_nC: 17; Vgs_V: 20; IdsMax_A: 23; SizeAreaWB_mm2: 58.1095; SizeArea_mm2: 31.5495; SizeX_mm: 6.15; SizeY_mm: 5.13; SizeZ_mm: 1.14; AEC Category: Q101; AEC Qualified: Y
R13 = CRCW060310R0FKEA: RES, 10.0, 1%, 0.1 W, 0603; Manufacturer: Vishay-Dale; CompType: Resistor; Value: 10.0; Res_ohm: 10; Value_Code: 10R0; Tolerance_%: 1; Power_W: 0.1; Value2: 0.1W; VDC_V: 75; TempCo: 100 ppm/C; SizeArea_mm2: 1.28; SizeX_mm: 1.6; SizeY_mm: 0.8; EIA_Code: E96; U/M: EA; AEC Category: Q200
R14 = CRCW12068R20JNEA: RES, 8.2, 5%, 0.25 W, 1206; Manufacturer: Vishay-Dale; CompType: Resistor; Value: 8.2; Value_Code: 8R20; Tolerance_%: 5; Power_W: 0.25; Value2: 0.25W; VDC_V: 200; TempCo: 200 ppm/C; SizeArea_mm2: 5.12; SizeX_mm: 3.2; SizeY_mm: 1.6; SizeZ_mm: 1.35; EIA_Code: E24; U/M: EA; AEC Category: Q200
R15 = CRCW06033R32FKEA: RES, 3.32, 1%, 0.1 W, 0603; Manufacturer: Vishay-Dale; CompType: Resistor; Value: 3.32; Value_Code: 3R32; Tolerance_%: 1; Power_W: 0.1; Value2: 0.1W; VDC_V: 75; TempCo: 100 ppm/C; SizeArea_mm2: 1.28; SizeX_mm: 1.6; SizeY_mm: 0.8; EIA_Code: E96; U/M: EA; AEC Category: Q200
R16 = CRCW060349K9FKEA: RES, 49.9 k, 1%, 0.1 W, 0603; Manufacturer: Vishay-Dale; CompType: Resistor; Value: 49.9k; Res_ohm: 49900; Value_Code: 49k9; Tolerance_%: 1; Power_W: 0.1; Value2: 0.1W; VDC_V: 75; TempCo: 100 ppm/C; EIA_Code: E96; U/M: EA; AEC Category: Q200; SizeArea_mm2: 1.28; SizeX_mm: 1.6; SizeY_mm: 0.8
R17 = CRCW06034R75FKEA: RES, 4.75, 1%, 0.1 W, 0603; Manufacturer: Vishay-Dale; CompType: Resistor; Value: 4.75; Value_Code: 4R75; Tolerance_%: 1; Power_W: 0.1; Value2: 0.1W; VDC_V: 75; TempCo: 100 ppm/C; SizeArea_mm2: 1.28; SizeX_mm: 1.6; SizeY_mm: 0.8; EIA_Code: E96; U/M: EA; AEC Category: Q200; Green_Lifecycle: Active; Green_REACh: Passed
R18 = CMP-0026763-1: RES, 100, 1%, 0.063 W, AEC-Q200 Grade 0, 0402; Manufacturer: Stackpole Electronics Inc; Power_W: 63mW; TempCo: 100 ppm/C; Value_Code: 100R; U/M: EA; Value: 100; EIA_Code: E96; SizeX_mm: 1; SizeY_mm: 0.5; SizeZ_mm: 0.6; Value2: 0.063W; AEC Qualified: Y; AEC Grade: 0; AEC Category: Q200
R19 = PRL1632-R008-F-T1: RES, 0.008, 1%, 1 W, 0612; Manufacturer: Susumu Co Ltd; CompType: Resistor; Value: 0.008; Value_Code: 8L000; Tolerance_%: 1; Value2: 1W; TempCo: 350 ppm/C; SizeArea_mm2: 5.12; SizeAreaWB_mm2: 10.92; SizeX_mm: 1.6; SizeY_mm: 3.2; SizeZ_mm: 0.85; EIA_Code: E96; U/M: EA; AEC Category: Q200
R20-R22 = CMP-0026992-3: RES, 0, 5%, 0.1 W, AEC-Q200 Grade 0, 0402; Manufacturer: Panasonic; Power_W: 100mW; TempCo: 600 ppm/C; Value_Code: 0000; Value: 0; EIA_Code: E24; SizeX_mm: 1; SizeY_mm: 0.5; SizeZ_mm: 0.6; Value2: 0.1W; AEC Qualified: Y; VDC_V: 50V; AEC Category: Q200; SizeAreaWB_mm2: 3
R23 = CMP-0026445-2: RES, 53.6 k, 1%, 0.063 W, AEC-Q200 Grade 0, 0402; Manufacturer: Vishay-Dale; Power_W: 63mW; TempCo: 100 ppm/C; Value_Code: 53k6; Value: 53.6k; EIA_Code: E96; SizeX_mm: 1; SizeY_mm: 0.5; SizeZ_mm: 0.6; Value2: 0.063W; AEC Qualified: Y; VDC_V: 50V; AEC Category: Q200; AEC Grade: 0
R24 = CMP-0026621-3: RES, 9.53 k, 1%, 0.063 W, AEC-Q200 Grade 0, 0402; Manufacturer: Vishay-Dale; Value_Code: 9k53; SizeX_mm: 1; Value: 9.53k; SizeY_mm: 0.5; AEC Category: Q200; AEC Qualified: Y; TempCo: 100 ppm/C; Power_W: 63mW; AEC Grade: 0; Value2: 0.063W; EIA_Code: E96; SizeZ_mm: 0.6; VDC_V: 50V
R25 = CMP-0026827-3: RES, 10, 5%, 0.063 W, AEC-Q200 Grade 0, 0402; Manufacturer: Vishay-Dale; Power_W: 63mW; TempCo: 200 ppm/C; Value_Code: 10R0; Value: 10; EIA_Code: E24; SizeX_mm: 1; SizeY_mm: 0.5; SizeZ_mm: 0.6; Value2: 0.063W; AEC Qualified: Y; VDC_V: 50V; AEC Category: Q200; AEC Grade: 0
R26 = CMP-0026159-2: RES, 200, 1%, 0.063 W, AEC-Q200 Grade 0, 0402; Manufacturer: Vishay-Dale; Power_W: 63mW; TempCo: 100 ppm/C; Value_Code: 200R; Value: 200; EIA_Code: E96; SizeX_mm: 1; SizeY_mm: 0.5; SizeZ_mm: 0.6; Value2: 0.063W; AEC Qualified: Y; VDC_V: 50V; AEC Category: Q200; AEC Grade: 0
TP8 TP10 = 5000: Test Point, Miniature, Red, TH; Manufacturer: Keystone; CompType: Test Point Loop; ContactFinish: Silver
TP9 TP11 = 5001: Test Point, Miniature, Black, TH; Manufacturer: Keystone; CompType: Test Point Loop; ContactFinish: Silver
U5 = LM5150RUMQ1: Wide VIN Automotive Low IQ Boost Controller, RUM0016C (WQFN-16); Manufacturer: Texas Instruments; SymbolCreator: a0411947; SizeArea_mm2: 16; SizeAreaWB_mm2: 25; SizeX_mm: 4; SizeZ_mm: 0.8; CompType: IC; U/M: EA

## Sheet PMP31245_Monitoring.SchDoc
size A4; Date: Not shown in title block; ApprovedBy: Not shown in title block; CheckedBy: Not shown in title block; Author: Not shown in title block; CompanyName: Not shown in title block; Engineer: Not shown in title block; Organization: Not shown in title block; Address1: Not shown in title block; Address2: Not shown in title block; Address3: Not shown in title block; Address4: Not shown in title block; DocumentNumber: 1; Revision: Use project parameter SCH_Rev; SheetNumber: 1; SheetTotal: 1; PageSetup: Record=PageOptions¦CenterHorizontal=True¦CenterVertical=True¦PrintScale=0.93¦XCorrection=1.00¦YCorrection=1.00¦PrintKind=0¦BorderSize=5000000¦LeftOffset=0¦BottomOffset=0¦Orientation=2¦PaperLength=1000¦PaperWidth=1000¦Scale=100¦PaperSource=15¦PrintQuality=600¦MediaType=1¦DitherType=10¦PaperKind=Letter¦PrintScaleMode=1
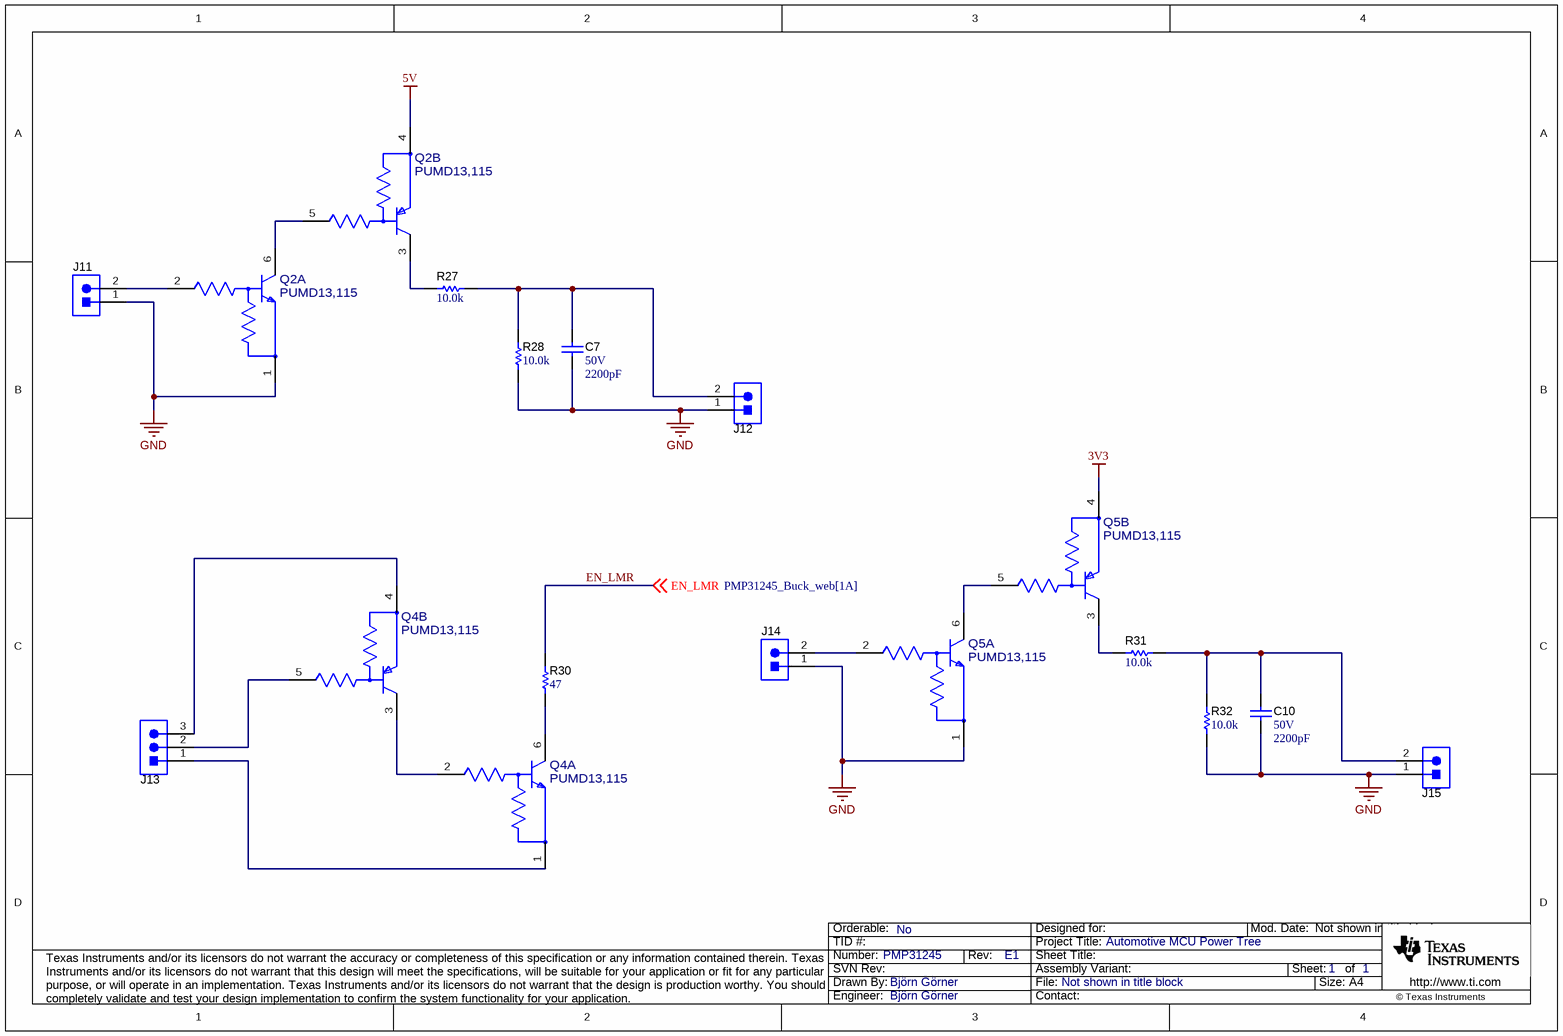
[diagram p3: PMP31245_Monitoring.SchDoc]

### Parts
C7  VDC_V: 50V  ValueDisplayed: 2200pF  [0402]  (hidden comment: CGA2B2X7R1H222K050BA)
C10  VDC_V: 50V  ValueDisplayed: 2200pF  [0402]  (hidden comment: CGA2B2X7R1H222K050BA)
J11  JEN  [Samtec_HTSW-102-07-G-S]  (value not drawn)
J12  JEN  [Samtec_HTSW-102-07-G-S]  (value not drawn)
J13  JMODE/SYNC  [Samtec_HTSW-103-07-G-S]  (value not drawn)
J14  JEN  [Samtec_HTSW-102-07-G-S]  (value not drawn)
J15  JEN  [Samtec_HTSW-102-07-G-S]  (value not drawn)
Q2  PUMD13,115  [FP-PUMD13,115_TSSOP6-MFG]  (parts A,B of 2)
Q4  PUMD13,115  [FP-PUMD13,115_TSSOP6-MFG]  (parts A,B of 2)
Q5  PUMD13,115  [FP-PUMD13,115_TSSOP6-MFG]  (parts A,B of 2)
R27  ValueDisplayed: 10.0k  [0402]  (hidden comment: AC0402FR-0710KL)
R28  ValueDisplayed: 10.0k  [0402]  (hidden comment: AC0402FR-0710KL)
R30  ValueDisplayed: 47  [0402]  (hidden comment: CRCW040247R0JNED)
R31  ValueDisplayed: 10.0k  [0402]  (hidden comment: AC0402FR-0710KL)
R32  ValueDisplayed: 10.0k  [0402]  (hidden comment: AC0402FR-0710KL)

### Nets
3V3: Q5.4(GND(emitter)TR2)
5V: Q2.4(GND(emitter)TR2)
GND: C7.2 C10.2 J11.1 J12.1 J14.1 J15.1 Q2.1(GND(emitter)TR1) Q5.1(GND(emitter)TR1) R28.1 R32.1
EN_LMR: R30.2 ; off-sheet EN_LMR
NetC7_1: C7.1 J12.2 R27.2 R28.2
NetC10_1: C10.1 J15.2 R31.2 R32.2
NetJ11_2: J11.2 Q2.2(input(base)TR1)
NetJ13_1: J13.1 Q4.1(GND(emitter)TR1)
NetJ13_2: J13.2 Q4.5(input(base)TR2)
NetJ13_3: J13.3 Q4.4(GND(emitter)TR2)
NetJ14_2: J14.2 Q5.2(input(base)TR1)
NetQ2_3: Q2.3(output(collector)TR2) R27.1
NetQ2_5: Q2.5(input(base)TR2) Q2.6(output(collector)TR1)
NetQ4_2: Q4.2(input(base)TR1) Q4.3(output(collector)TR2)
NetQ4_6: Q4.6(output(collector)TR1) R30.1
NetQ5_3: Q5.3(output(collector)TR2) R31.1
NetQ5_5: Q5.5(input(base)TR2) Q5.6(output(collector)TR1)

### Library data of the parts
C7 C10 = CMP-0006317-2: as C43 on sheet PMP31245_Boost
J11 J12 J14 J15 = CMP-0075483-1: as J2 on sheet PMP31245_Buck_web
J13 = CMP-0075484-1: as J4 on sheet PMP31245_Buck_web
Q2 Q4 Q5 = CMP-0092475-1: Trans Digital BJT NPN/PNP 50V 100mA 300mW Automotive 6-Pin TSSOP T/R; Manufacturer: Nexperia; Number Of Pnp: 1; Vcesat1_V: 100mV; TaMax_C: 150°C; TaMin_C: -65°C; AEC Grade: Grade 0; Rthja Max: 417K/W; Emitter Base Voltage: 5V; Number Of Elements: 2; SizeZ_mm: 1.1mm; Hfe Testic: 10mA; Unity Gain Freq: 230/180MHz; TJmax_C: +150°C; AEC Qualified: Yes; Hfe Min: 100
R27 R28 R31 R32 = CMP-0077731-1: RES, 10.0 k, 1%, 0.063 W, AEC-Q200 Grade 0, 0402; Manufacturer: Yageo America; Power_W: 63mW; TempCo: 100 ppm/C; Value_Code: 10k0; U/M: EA; Value: 10.0k; EIA_Code: E96; Res_ohm: 10k; SizeX_mm: 1.0; SizeY_mm: 0.5; SizeZ_mm: 0.6; Value2: 0.063W; AEC Qualified: Y; VDC_V: 50V; AEC Grade: 0; AEC Category: Q200
R30 = CMP-0026936-3: RES, 47, 5%, 0.063 W, AEC-Q200 Grade 0, 0402; Manufacturer: Vishay-Dale; Power_W: 63mW; TempCo: 200 ppm/C; Value_Code: 47R0; Value: 47; EIA_Code: E24; SizeX_mm: 1; SizeY_mm: 0.5; SizeZ_mm: 0.6; Value2: 0.063W; AEC Qualified: Y; VDC_V: 50V; AEC Category: Q200; AEC Grade: 0

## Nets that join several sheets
3V3: PMP31245_Buck_web (10 pins), PMP31245_Monitoring (Q5.4)
5V: PMP31245_Buck_web (23 pins), PMP31245_Monitoring (Q2.4)
12V: PMP31245_Buck_web (C1.2 C2.1 R1.2 U1.4), PMP31245_Boost (14 pins)
GND: PMP31245_Buck_web (50 pins), PMP31245_Boost (31 pins), PMP31245_Monitoring (10 pins)
EN_LMR: PMP31245_Buck_web (J2.2 R1.1 U1.3), PMP31245_Monitoring (R30.2)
